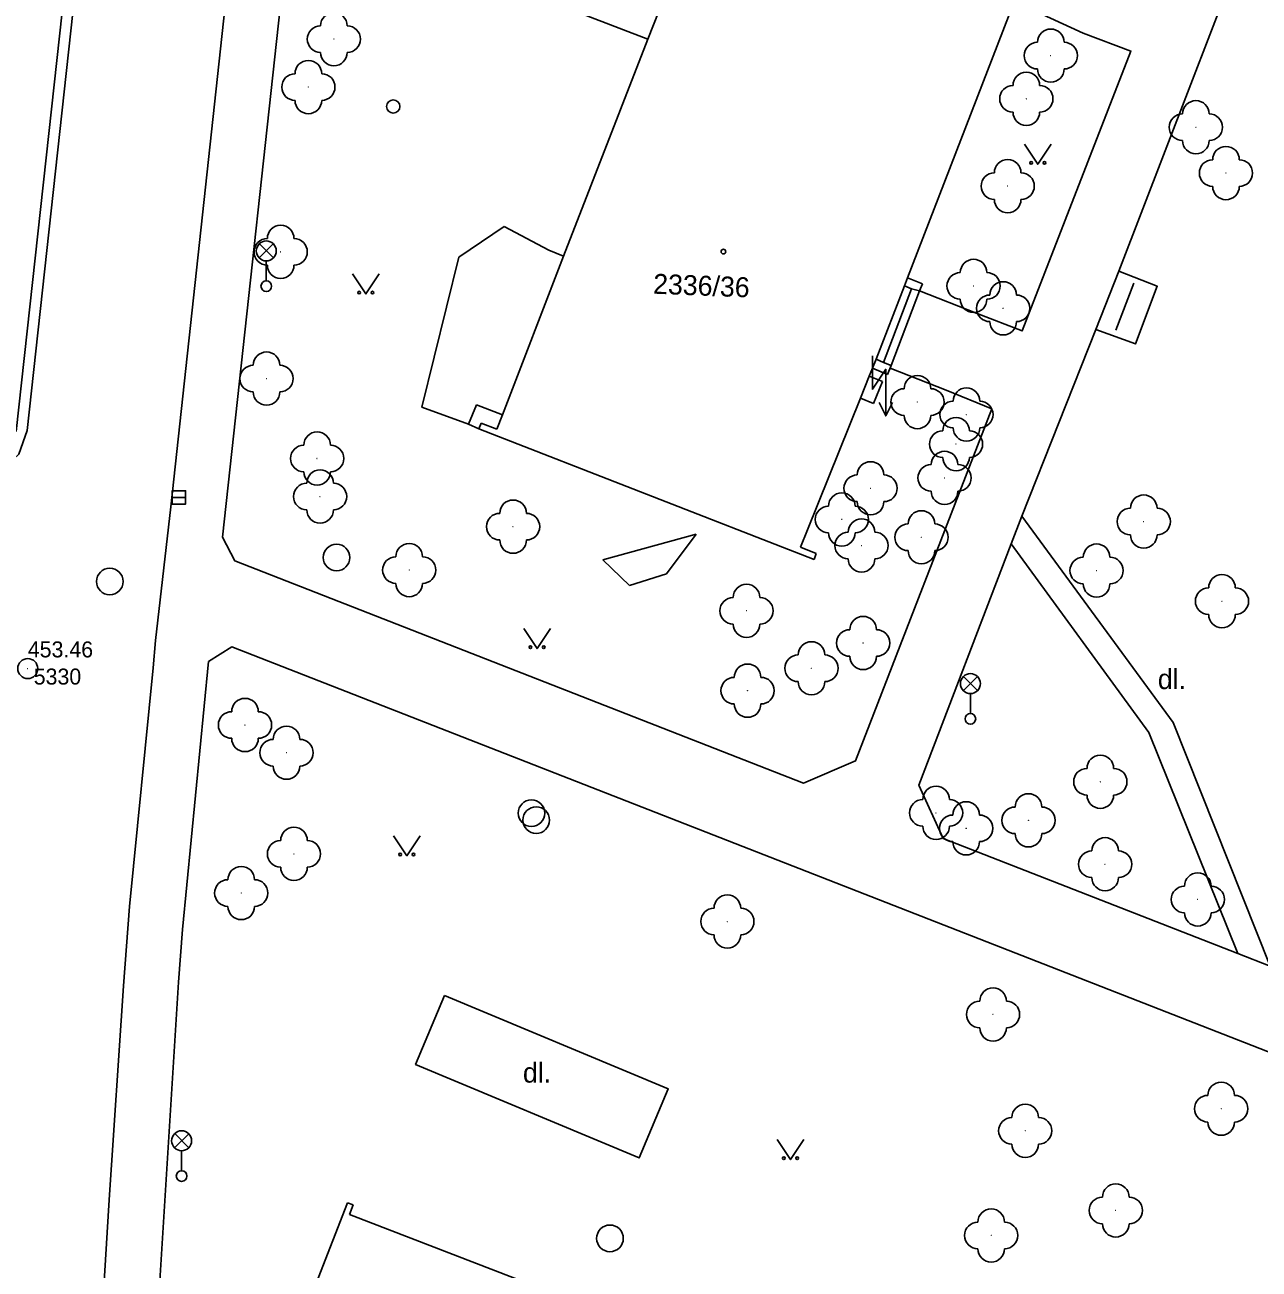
# Model space of a CAD drawing. Extents: x -737812 to -729375, y -1123000 to -1115500.
# Drawn here: x -736826.17 to -736779.81, y -1118482.39 to -1118435.66 of the extents above; entities that cross this region are included whole.
import ezdxf

# ---------------------------------------------------------------- set-up
doc = ezdxf.new("R2010")
doc.units = 0
for name, color, linetype in [('Doplněk polohopisu', 7, 'Continuous'), ('Hranice - ploty_ zdi', 7, 'Continuous'), ('Komunikace', 7, 'Continuous'), ('Pomocné popisy', 7, 'Continuous'), ('Povr_ zn_ inž_ sítí - el_', 7, 'Continuous'), ('Povr_ zn_ inž_ sítí - kan_', 7, 'Continuous'), ('Povr_ zn_ inž_ sítí - vod_', 7, 'Continuous'), ('Stavební objekty', 7, 'Continuous'), ('Zeleň', 7, 'Continuous'), ('Značky bodového  pole', 7, 'Continuous'), ('Značky druhů budov', 7, 'Continuous'), ('Značky druhů pozemků', 7, 'Continuous'), ('Čísla popisná', 7, 'Continuous')]:
    doc.layers.add(name, color=color, linetype=linetype)

msp = doc.modelspace()

# ---------------------------------------------------------------- linework, layer by layer
at = {"layer": 'Doplněk polohopisu'}
for p, q in [((-736785.94, -1118447.1), (-736785.08, -1118444.9)), ((-736785.19, -1118447.12), (-736784.51, -1118445.36)), ((-736789.12, -1118455.14), (-736788.72, -1118454.11)), ((-736780.61, -1118470.53), (-736779.39, -1118471.01))]:
    msp.add_line(p, q, dxfattribs=at)
for points in [[(-736788.72, -1118454.11), (-736783.04, -1118461.86), (-736779.39, -1118471.01), (-736769.98, -1118474.7), (-736769.35, -1118473.26), (-736760.6, -1118450.66), (-736756.75, -1118440.39), (-736755.79, -1118437.87), (-736778.95, -1118428.99), (-736785.08, -1118444.9), (-736783.63, -1118445.47), (-736784.45, -1118447.64), (-736785.94, -1118447.1)], [(-736793.66, -1118448.55), (-736791.56, -1118449.38), (-736789.85, -1118450.07), (-736794.97, -1118463.3), (-736796.92, -1118464.14), (-736818.28, -1118455.79), (-736818.74, -1118454.89), (-736816.15, -1118431.09), (-736810.04, -1118433.39), (-736802.77, -1118436.19)], [(-736792.56, -1118445.64), (-736790.4, -1118446.49), (-736788.7, -1118447.15), (-736784.62, -1118436.64), (-736786.41, -1118435.97), (-736788.41, -1118435.05)], [(-736785.94, -1118447.1), (-736788.72, -1118454.11)], [(-736789.12, -1118455.14), (-736792.59, -1118464.21), (-736791.67, -1118466.21), (-736780.61, -1118470.53), (-736783.95, -1118462.23), (-736789.12, -1118455.14)], [(-736821.96, -1118496.65), (-736820.4, -1118471.61), (-736820.25, -1118469.63), (-736819.27, -1118459.57), (-736818.4, -1118459.02), (-736778.98, -1118474.41)], [(-736810.4, -1118472.11), (-736802, -1118475.62), (-736803.09, -1118478.21), (-736811.49, -1118474.7), (-736810.4, -1118472.11)]]:
    msp.add_lwpolyline(points, dxfattribs=at)
at = {"layer": 'Hranice - ploty_ zdi'}
for points in [[(-736826.5, -1118450.93), (-736822.31, -1118412.77)], [(-736793.01, -1118445.16), (-736792.45, -1118445.38)], [(-736792.86, -1118445.57), (-736793.92, -1118448.33)], [(-736793.13, -1118445.46), (-736792.86, -1118445.57), (-736792.56, -1118445.64)], [(-736792.45, -1118445.38), (-736792.56, -1118445.64)], [(-736793.63, -1118448.45), (-736792.56, -1118445.64)], [(-736794.19, -1118448.21), (-736793.92, -1118448.33), (-736793.63, -1118448.45)], [(-736794.33, -1118448.55), (-736793.76, -1118448.78)], [(-736793.63, -1118448.45), (-736793.76, -1118448.78)], [(-736809.21, -1118449.92), (-736809.51, -1118450.65)], [(-736808.23, -1118450.3), (-736809.21, -1118449.92)], [(-736809.51, -1118450.65), (-736809.11, -1118450.83)]]:
    msp.add_lwpolyline(points, dxfattribs=at)
at = {"layer": 'Komunikace'}
for points in [[(-736819.01, -1118355.75), (-736819.78, -1118369.97), (-736817.48, -1118372.37), (-736821.29, -1118407.1), (-736824.12, -1118432.89), (-736826.08, -1118450.89), (-736826.39, -1118451.78), (-736827.11, -1118452.43), (-736827.55, -1118452.67), (-736828.44, -1118452.83), (-736829.57, -1118452.71)], [(-736824.89, -1118510.71), (-736823, -1118479.78), (-736822.47, -1118471.75), (-736822.24, -1118468.77), (-736821.35, -1118459.8), (-736821.26, -1118458.78), (-736820.69, -1118453.76), (-736818.08, -1118429.73), (-736812.77, -1118381.57), (-736812.39, -1118378.17), (-736812.28, -1118377.15), (-736811.94, -1118374.18), (-736811.83, -1118373.18), (-736810.48, -1118361.25)]]:
    msp.add_lwpolyline(points, dxfattribs=at)
at = {"layer": 'Povr_ zn_ inž_ sítí - el_'}
for p, q in [((-736817.364, -1118444.408), (-736816.836, -1118443.88)), ((-736816.828, -1118444.405), (-736817.356, -1118443.876)), ((-736817.1, -1118444.52), (-736817.1, -1118445.27)), ((-736790.914, -1118460.658), (-736790.386, -1118460.13)), ((-736790.378, -1118460.655), (-736790.906, -1118460.126)), ((-736790.65, -1118460.77), (-736790.65, -1118461.52)), ((-736820.544, -1118477.828), (-736820.016, -1118477.3)), ((-736820.008, -1118477.825), (-736820.536, -1118477.296)), ((-736820.28, -1118477.94), (-736820.28, -1118478.69))]:
    msp.add_line(p, q, dxfattribs=at)
for points in [[(-736794.33, -1118448.09), (-736794.33, -1118449.34), (-736793.83, -1118448.59), (-736793.83, -1118450.34)], [(-736794.08, -1118449.84), (-736793.83, -1118450.34), (-736793.58, -1118449.84)]]:
    msp.add_lwpolyline(points, dxfattribs=at)
for centre, radius in [((-736817.1, -1118444.145), 0.375), ((-736817.1, -1118445.47), 0.2), ((-736790.65, -1118460.395), 0.375), ((-736790.65, -1118461.72), 0.2), ((-736820.28, -1118477.565), 0.375), ((-736820.28, -1118478.89), 0.2)]:
    msp.add_circle(centre, radius, dxfattribs=at)
at = {"layer": 'Povr_ zn_ inž_ sítí - kan_'}
msp.add_line((-736820.63, -1118453.4), (-736820.13, -1118453.4), dxfattribs=at)
msp.add_lwpolyline([(-736820.63, -1118453.651), (-736820.129, -1118453.651), (-736820.129, -1118453.149), (-736820.63, -1118453.149)], close=True, dxfattribs=at)
for centre in [(-736814.46, -1118455.66), (-736822.98, -1118456.56), (-736807.14, -1118465.26), (-736806.96, -1118465.52), (-736804.19, -1118481.23)]:
    msp.add_circle(centre, 0.5, dxfattribs=at)
at = {"layer": 'Povr_ zn_ inž_ sítí - vod_'}
msp.add_circle((-736812.33, -1118438.72), 0.25, dxfattribs=at)
at = {"layer": 'Stavební objekty'}
for points in [[(-736784.96, -1118390.1), (-736785.09, -1118390.45), (-736790.55, -1118404.55), (-736791.13, -1118406.09), (-736802.34, -1118435.11), (-736802.77, -1118436.19), (-736805.93, -1118444.34), (-736808.23, -1118450.3), (-736808.44, -1118450.84)], [(-736794.19, -1118448.21), (-736793.13, -1118445.46), (-736793.01, -1118445.16), (-736789.01, -1118434.79)], [(-736797.03, -1118455.27), (-736796.77, -1118454.62), (-736794.78, -1118449.68), (-736794.45, -1118448.85), (-736794.33, -1118448.55), (-736794.19, -1118448.21)], [(-736793.95, -1118449.05), (-736794.45, -1118448.85)], [(-736794.29, -1118449.88), (-736793.95, -1118449.05)], [(-736794.29, -1118449.88), (-736794.78, -1118449.68)], [(-736809.11, -1118450.83), (-736809.03, -1118450.61)], [(-736809.03, -1118450.61), (-736808.44, -1118450.84)], [(-736809.11, -1118450.83), (-736796.52, -1118455.73)], [(-736797.03, -1118455.27), (-736796.44, -1118455.51)], [(-736796.52, -1118455.73), (-736796.44, -1118455.51)], [(-736818.83, -1118492.18), (-736814.05, -1118479.9)], [(-736814.05, -1118479.9), (-736813.84, -1118479.97)], [(-736813.84, -1118479.97), (-736813.97, -1118480.33)], [(-736783.7, -1118492.02), (-736813.97, -1118480.33)]]:
    msp.add_lwpolyline(points, dxfattribs=at)
at = {"layer": 'Zeleň'}
for points in [[(-736809.87, -1118444.38), (-736808.16, -1118443.23)], [(-736808.16, -1118443.23), (-736806.49, -1118444.12)], [(-736806.49, -1118444.12), (-736805.93, -1118444.34)], [(-736811.26, -1118450.01), (-736809.87, -1118444.38)], [(-736809.51, -1118450.65), (-736811.26, -1118450.01)], [(-736800.95, -1118454.78), (-736804.46, -1118455.74)], [(-736802.07, -1118456.27), (-736800.95, -1118454.78)], [(-736804.46, -1118455.74), (-736803.46, -1118456.71)], [(-736803.46, -1118456.71), (-736802.07, -1118456.27)]]:
    msp.add_lwpolyline(points, dxfattribs=at)
for centre in [(-736814.56, -1118436.19), (-736787.63, -1118436.81), (-736815.52, -1118437.99), (-736788.55, -1118438.43), (-736782.18, -1118439.5), (-736781.05, -1118441.22), (-736789.25, -1118441.71), (-736816.56, -1118444.18), (-736790.53, -1118445.46), (-736789.42, -1118446.3), (-736817.09, -1118448.94), (-736792.64, -1118449.82), (-736790.8, -1118450.29), (-736791.19, -1118451.4), (-736815.19, -1118451.94), (-736794.4, -1118453.06), (-736791.62, -1118452.67), (-736815.08, -1118453.37), (-736807.83, -1118454.5), (-736795.48, -1118454.23), (-736784.14, -1118454.31), (-736792.49, -1118454.9), (-736794.74, -1118455.21), (-736811.73, -1118456.13), (-736785.91, -1118456.15), (-736781.2, -1118457.3), (-736799.06, -1118457.66), (-736794.68, -1118458.87), (-736796.62, -1118459.82), (-736799.02, -1118460.66), (-736817.9, -1118461.95), (-736816.34, -1118462.99), (-736785.77, -1118464.08), (-736791.94, -1118465.25), (-736788.47, -1118465.53), (-736790.81, -1118465.83), (-736816.06, -1118466.79), (-736785.59, -1118467.18), (-736818.04, -1118468.26), (-736782.11, -1118468.5), (-736799.78, -1118469.33), (-736789.8, -1118472.82), (-736781.23, -1118476.36), (-736788.59, -1118477.19), (-736785.19, -1118480.18), (-736789.87, -1118481.12)]:
    msp.add_circle(centre, 0.0005, dxfattribs=at)
for centre, start, end in [((-736814.56, -1118435.69), 0, 180), ((-736815.06, -1118436.19), 90, 270), ((-736814.06, -1118436.19), 270, 90), ((-736787.63, -1118436.31), 360, 180), ((-736814.56, -1118436.69), 180, 360), ((-736788.13, -1118436.81), 90, 270), ((-736787.13, -1118436.81), 270, 90), ((-736815.52, -1118437.49), 360, 180), ((-736816.02, -1118437.99), 90, 270), ((-736815.02, -1118437.99), 270, 90), ((-736788.55, -1118437.93), 360, 180), ((-736787.63, -1118437.31), 180, 360), ((-736789.05, -1118438.43), 90, 270), ((-736788.05, -1118438.43), 270, 90), ((-736815.52, -1118438.49), 180, 360), ((-736782.18, -1118439), 360, 180), ((-736788.55, -1118438.93), 180, 360), ((-736782.68, -1118439.5), 90, 270), ((-736781.68, -1118439.5), 270, 90), ((-736782.18, -1118440), 180, 360), ((-736781.05, -1118440.72), 360, 180), ((-736789.25, -1118441.21), 360, 180), ((-736781.55, -1118441.22), 90, 270), ((-736780.55, -1118441.22), 270, 90), ((-736789.75, -1118441.71), 90, 270), ((-736788.75, -1118441.71), 270, 90), ((-736781.05, -1118441.72), 180, 360), ((-736789.25, -1118442.21), 180, 360), ((-736816.56, -1118443.68), 360, 180), ((-736817.06, -1118444.18), 90, 270), ((-736816.06, -1118444.18), 270, 90), ((-736816.56, -1118444.68), 180, 360), ((-736790.53, -1118444.96), 360, 180), ((-736791.03, -1118445.46), 90, 270), ((-736790.03, -1118445.46), 270, 90), ((-736789.42, -1118445.8), 360, 180), ((-736790.53, -1118445.96), 180, 360), ((-736789.92, -1118446.3), 90, 270), ((-736788.92, -1118446.3), 270, 90), ((-736789.42, -1118446.8), 180, 360), ((-736817.09, -1118448.44), 360, 180), ((-736817.59, -1118448.94), 90, 270), ((-736816.59, -1118448.94), 270, 90), ((-736792.64, -1118449.32), 360, 180), ((-736793.14, -1118449.82), 90, 270), ((-736792.14, -1118449.82), 270, 90), ((-736790.8, -1118449.79), 360, 180), ((-736817.09, -1118449.44), 180, 360), ((-736791.3, -1118450.29), 90, 270), ((-736790.3, -1118450.29), 270, 90), ((-736792.64, -1118450.32), 180, 360), ((-736791.19, -1118450.9), 360, 180), ((-736815.19, -1118451.44), 360, 180), ((-736791.69, -1118451.4), 90, 270), ((-736790.8, -1118450.79), 180, 360), ((-736790.69, -1118451.4), 270, 90), ((-736815.69, -1118451.94), 90, 270), ((-736814.69, -1118451.94), 270, 90), ((-736791.62, -1118452.17), 360, 180), ((-736794.4, -1118452.56), 360, 180), ((-736792.12, -1118452.67), 90, 270), ((-736791.19, -1118451.9), 180, 360), ((-736791.12, -1118452.67), 270, 90), ((-736815.19, -1118452.44), 180, 360), ((-736815.08, -1118452.87), 360, 180), ((-736794.9, -1118453.06), 90, 270), ((-736793.9, -1118453.06), 270, 90), ((-736815.58, -1118453.37), 90, 270), ((-736814.58, -1118453.37), 270, 90), ((-736807.83, -1118454), 360, 180), ((-736795.48, -1118453.73), 360, 180), ((-736794.4, -1118453.56), 180, 360), ((-736791.62, -1118453.17), 180, 360), ((-736784.14, -1118453.81), 360, 180), ((-736815.08, -1118453.87), 180, 360), ((-736808.33, -1118454.5), 90, 270), ((-736807.33, -1118454.5), 270, 90), ((-736795.98, -1118454.23), 90, 270), ((-736794.98, -1118454.23), 270, 90), ((-736792.49, -1118454.4), 360, 180), ((-736784.64, -1118454.31), 90, 270), ((-736783.64, -1118454.31), 270, 90), ((-736794.74, -1118454.71), 360, 180), ((-736792.99, -1118454.9), 90, 270), ((-736791.99, -1118454.9), 270, 90), ((-736795.48, -1118454.73), 180, 360), ((-736795.24, -1118455.21), 90, 270), ((-736794.24, -1118455.21), 270, 90), ((-736784.14, -1118454.81), 180, 360), ((-736811.73, -1118455.63), 360, 180), ((-736807.83, -1118455), 180, 360), ((-736792.49, -1118455.4), 180, 360), ((-736785.91, -1118455.65), 360, 180), ((-736812.23, -1118456.13), 90, 270), ((-736811.23, -1118456.13), 270, 90), ((-736794.74, -1118455.71), 180, 360), ((-736786.41, -1118456.15), 90, 270), ((-736785.41, -1118456.15), 270, 90), ((-736781.2, -1118456.8), 360, 180), ((-736811.73, -1118456.63), 180, 360), ((-736799.06, -1118457.16), 360, 180), ((-736785.91, -1118456.65), 180, 360), ((-736781.7, -1118457.3), 90, 270), ((-736780.7, -1118457.3), 270, 90), ((-736799.56, -1118457.66), 90, 270), ((-736798.56, -1118457.66), 270, 90), ((-736799.06, -1118458.16), 180, 360), ((-736794.68, -1118458.37), 360, 180), ((-736781.2, -1118457.8), 180, 360), ((-736795.18, -1118458.87), 90, 270), ((-736794.18, -1118458.87), 270, 90), ((-736796.62, -1118459.32), 360, 180), ((-736797.12, -1118459.82), 90, 270), ((-736796.12, -1118459.82), 270, 90), ((-736794.68, -1118459.37), 180, 360), ((-736799.02, -1118460.16), 360, 180), ((-736799.52, -1118460.66), 90, 270), ((-736798.52, -1118460.66), 270, 90), ((-736796.62, -1118460.32), 180, 360), ((-736817.9, -1118461.45), 360, 180), ((-736818.4, -1118461.95), 90, 270), ((-736817.4, -1118461.95), 270, 90), ((-736799.02, -1118461.16), 180, 360), ((-736817.9, -1118462.45), 180, 360), ((-736816.34, -1118462.49), 360, 180), ((-736816.84, -1118462.99), 90, 270), ((-736815.84, -1118462.99), 270, 90), ((-736785.77, -1118463.58), 360, 180), ((-736816.34, -1118463.49), 180, 360), ((-736786.27, -1118464.08), 90, 270), ((-736785.27, -1118464.08), 270, 90), ((-736791.94, -1118464.75), 360, 180), ((-736792.44, -1118465.25), 90, 270), ((-736791.44, -1118465.25), 270, 90), ((-736788.47, -1118465.03), 360, 180), ((-736785.77, -1118464.58), 180, 360), ((-736790.81, -1118465.33), 360, 180), ((-736788.97, -1118465.53), 90, 270), ((-736787.97, -1118465.53), 270, 90), ((-736791.31, -1118465.83), 90, 270), ((-736790.31, -1118465.83), 270, 90), ((-736816.06, -1118466.29), 360, 180), ((-736791.94, -1118465.75), 180, 360), ((-736788.47, -1118466.03), 180, 360), ((-736785.59, -1118466.68), 360, 180), ((-736816.56, -1118466.79), 90, 270), ((-736815.56, -1118466.79), 270, 90), ((-736790.81, -1118466.33), 180, 360), ((-736786.09, -1118467.18), 90, 270), ((-736785.09, -1118467.18), 270, 90), ((-736818.04, -1118467.76), 360, 180), ((-736816.06, -1118467.29), 180, 360), ((-736782.11, -1118468), 360, 180), ((-736818.54, -1118468.26), 90, 270), ((-736817.54, -1118468.26), 270, 90), ((-736785.59, -1118467.68), 180, 360), ((-736782.61, -1118468.5), 90, 270), ((-736781.61, -1118468.5), 270, 90), ((-736799.78, -1118468.83), 360, 180), ((-736818.04, -1118468.76), 180, 360), ((-736800.28, -1118469.33), 90, 270), ((-736799.28, -1118469.33), 270, 90), ((-736782.11, -1118469), 180, 360), ((-736799.78, -1118469.83), 180, 360), ((-736789.8, -1118472.32), 360, 180), ((-736790.3, -1118472.82), 90, 270), ((-736789.3, -1118472.82), 270, 90), ((-736789.8, -1118473.32), 180, 360), ((-736781.23, -1118475.86), 360, 180), ((-736781.73, -1118476.36), 90, 270), ((-736780.73, -1118476.36), 270, 90), ((-736788.59, -1118476.69), 360, 180), ((-736789.09, -1118477.19), 90, 270), ((-736788.09, -1118477.19), 270, 90), ((-736781.23, -1118476.86), 180, 360), ((-736788.59, -1118477.69), 180, 360), ((-736785.19, -1118479.68), 360, 180), ((-736785.69, -1118480.18), 90, 270), ((-736784.69, -1118480.18), 270, 90), ((-736789.87, -1118480.62), 360, 180), ((-736790.37, -1118481.12), 90, 270), ((-736789.37, -1118481.12), 270, 90), ((-736785.19, -1118480.68), 180, 360), ((-736789.87, -1118481.62), 180, 360)]:
    msp.add_arc(centre, 0.5, start, end, dxfattribs=at)
at = {"layer": 'Značky bodového  pole'}
for radius in [0.375, 0.0005]:
    msp.add_circle((-736826.06, -1118459.83), radius, dxfattribs=at)
at = {"layer": 'Značky druhů budov'}
msp.add_circle((-736799.929, -1118444.17), 0.0875, dxfattribs=at)
at = {"layer": 'Značky druhů pozemků'}
for points in [[(-736788.62, -1118440.14), (-736788.12, -1118440.89), (-736787.62, -1118440.14)], [(-736813.86, -1118445.01), (-736813.36, -1118445.76), (-736812.86, -1118445.01)], [(-736807.43, -1118458.33), (-736806.93, -1118459.08), (-736806.43, -1118458.33)], [(-736812.32, -1118466.11), (-736811.82, -1118466.86), (-736811.32, -1118466.11)], [(-736797.91, -1118477.52), (-736797.41, -1118478.27), (-736796.91, -1118477.52)]]:
    msp.add_lwpolyline(points, dxfattribs=at)
for centre in [(-736788.37, -1118440.84), (-736787.87, -1118440.84), (-736813.61, -1118445.71), (-736813.11, -1118445.71), (-736807.18, -1118459.03), (-736806.68, -1118459.03), (-736812.07, -1118466.81), (-736811.57, -1118466.81), (-736797.66, -1118478.22), (-736797.16, -1118478.22)]:
    msp.add_circle(centre, 0.05, dxfattribs=at)

# ---------------------------------------------------------------- texts
at = {"layer": 'Pomocné popisy'}
for p in [(-736783.61, -1118460.6), (-736807.46, -1118475.38)]:
    msp.add_text('dl.', height=0.75, dxfattribs=at).set_placement(p)
at = {"layer": 'Značky bodového  pole'}
for s, p in [('453.46', (-736826.06, -1118459.41)), (' 5330', (-736826.06, -1118460.43))]:
    msp.add_text(s, height=0.6, dxfattribs=at).set_placement(p)
at = {"layer": 'Čísla popisná'}
msp.add_text('2336/36', height=0.75, rotation=357.763, dxfattribs=at).set_placement((-736802.58, -1118445.75))

doc.saveas('drawing.dxf')
